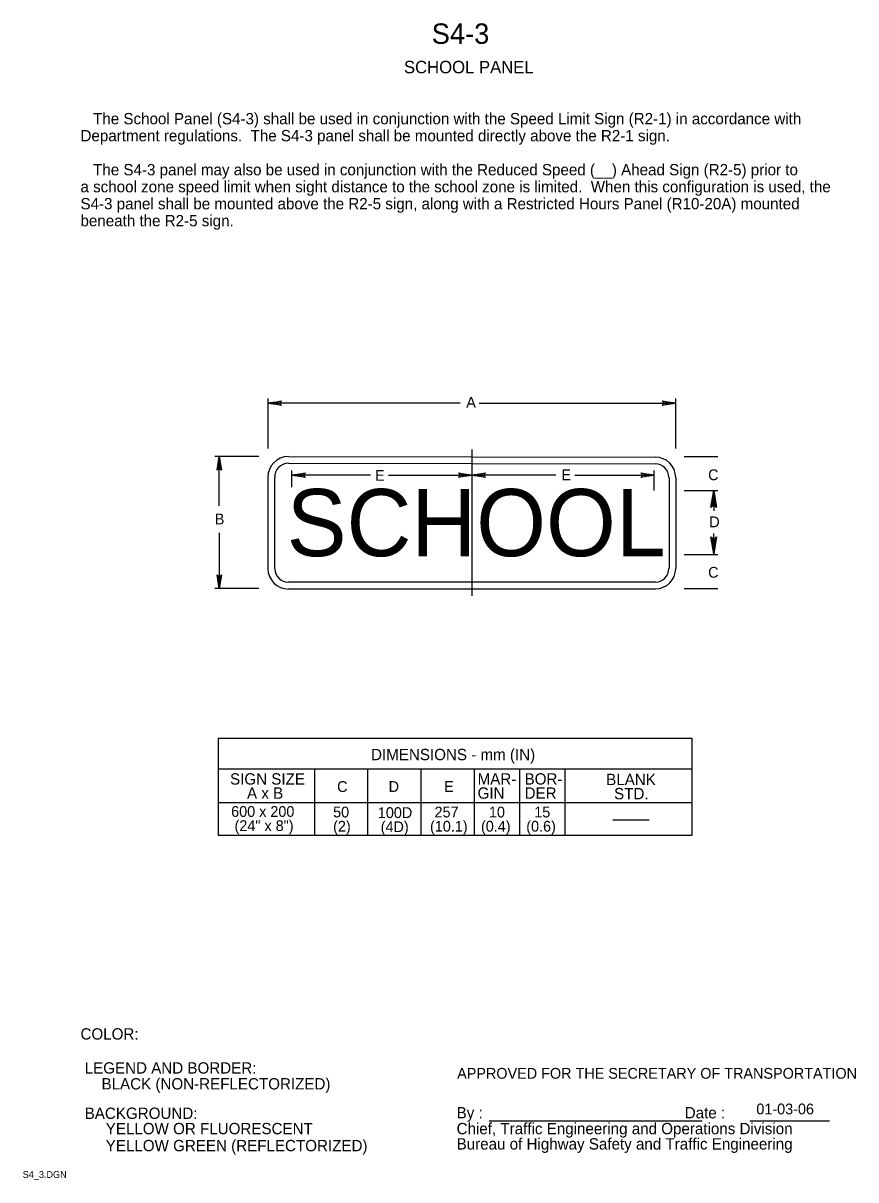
# Model space of a CAD drawing. Extents: x 0.013 to 0.196, y 0.004 to 0.259.
import ezdxf

# ---------------------------------------------------------------- set-up
doc = ezdxf.new("R2010")
doc.units = 0
for name, color, linetype in [('1', 7, 'Continuous'), ('2', 7, 'Continuous'), ('3', 7, 'Continuous'), ('4', 7, 'Continuous')]:
    doc.layers.add(name, color=color, linetype=linetype)

# ---------------------------------------------------------------- blocks, each defined once
blk = doc.blocks.new('RARROW')
at = {"layer": '3'}
for p, q in [((-2.156, 0.285), (-2.2665, 0.384625)), ((-2.2665, 0.384625), (0, 0)), ((0, 0), (-2.2665, -0.379125)), ((-2.156, 0.285), (-2.075625, 0.12075)), ((0, 0), (-2.156, 0.285)), ((-2.14975, -0.2705), (0, 0)), ((-2.075625, 0.12075), (0, 0)), ((0, 0), (-2.074, -0.108)), ((-2.2665, -0.379125), (-2.14975, -0.2705)), ((-2.074, -0.108), (-2.14975, -0.2705))]:
    blk.add_line(p, q, dxfattribs=at)

msp = doc.modelspace()

# ---------------------------------------------------------------- linework, layer by layer
at = {"layer": '1'}
for p, q in [((0.11163, 0.165), (0.11163, 0.13275)), ((0.11544, 0.01695), (0.16242, 0.01695)), ((0.17295, 0.01695), (0.19056, 0.01695))]:
    msp.add_line(p, q, dxfattribs=at)
at = {"layer": '3'}
for p, q in [((0.06663, 0.16525), (0.06663, 0.17625)), ((0.15663, 0.16525), (0.15663, 0.17625)), ((0.109, 0.17525), (0.06663, 0.17525)), ((0.11325, 0.17525), (0.15663, 0.17525)), ((0.06459, 0.1635), (0.05488, 0.1635)), ((0.05588, 0.15263), (0.05588, 0.1635)), ((0.07113, 0.1635), (0.15213, 0.16337)), ((0.1585, 0.1635), (0.16587, 0.1635)), ((0.07113, 0.162), (0.15213, 0.16187)), ((0.11163, 0.16225), (0.11163, 0.16037)), ((0.06663, 0.13875), (0.06663, 0.15888)), ((0.06813, 0.13875), (0.06813, 0.15888)), ((0.07188, 0.15675), (0.07188, 0.16037)), ((0.08925, 0.15938), (0.07188, 0.15938)), ((0.09325, 0.15938), (0.11163, 0.15938)), ((0.13012, 0.15938), (0.11163, 0.15938)), ((0.13437, 0.15938), (0.15188, 0.15938)), ((0.15188, 0.156), (0.15188, 0.16037)), ((0.15513, 0.15888), (0.15513, 0.13875)), ((0.15663, 0.15888), (0.15663, 0.13875)), ((0.1585, 0.156), (0.16587, 0.156)), ((0.165, 0.156), (0.165, 0.1515)), ((0.05588, 0.14663), (0.05588, 0.13437)), ((0.165, 0.142), (0.165, 0.1465)), ((0.1585, 0.14188), (0.16587, 0.14188)), ((0.15213, 0.13575), (0.07113, 0.13575)), ((0.06459, 0.13437), (0.05488, 0.13437)), ((0.15213, 0.13425), (0.07113, 0.13425)), ((0.1585, 0.13437), (0.16587, 0.13437)), ((0.05563, 0.10138), (0.16012, 0.10138)), ((0.05563, 0.10138), (0.05563, 0.07988)), ((0.16012, 0.10138), (0.16012, 0.07988)), ((0.16012, 0.0945), (0.05563, 0.0945)), ((0.07687, 0.0945), (0.07687, 0.07988)), ((0.07687, 0.0945), (0.07687, 0.08113)), ((0.08862, 0.0945), (0.08862, 0.07988)), ((0.10038, 0.0945), (0.10038, 0.07988)), ((0.11213, 0.0945), (0.11213, 0.07988)), ((0.12212, 0.0945), (0.12212, 0.07988)), ((0.13212, 0.0945), (0.13212, 0.07988)), ((0.16012, 0.08713), (0.05563, 0.08713)), ((0.14275, 0.08338), (0.15075, 0.08338)), ((0.16012, 0.07988), (0.05563, 0.07988))]:
    msp.add_line(p, q, dxfattribs=at)
for centre, radius, start, end in [((0.07119, 0.15891), 0.00459, 90.7913, 180.7913), ((0.1521, 0.15885), 0.0045, 0, 90), ((0.07119, 0.15891), 0.00309, 91.1755, 181.1755), ((0.1521, 0.15885), 0.003, 0, 90), ((0.07113, 0.13878), 0.00453, 179.9414, 269.9414), ((0.07109, 0.13875), 0.00297, 180.0894, 270.0894), ((0.1521, 0.13879), 0.0045, 270, 0), ((0.1521, 0.13879), 0.003, 270, 0)]:
    msp.add_arc(centre, radius, start, end, dxfattribs=at)

# ---------------------------------------------------------------- block references
for p, xscale, yscale, rotation in [((0.06663, 0.17525), 0.0013236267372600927, 0.001309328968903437, 180), ((0.05588, 0.1635), 0.0013236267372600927, 0.001309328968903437, 90), ((0.07188, 0.15938), 0.0013236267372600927, 0.001309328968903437, 180), ((0.11163, 0.15938), 0.0013236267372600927, 0.001309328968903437, 180), ((0.165, 0.156), 0.0016545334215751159, 0.0016366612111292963, 90), ((0.165, 0.142), 0.0016545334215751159, 0.0016366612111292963, -90), ((0.05588, 0.13437), 0.0013236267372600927, 0.001309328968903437, -90)]:
    msp.add_blockref('RARROW', p, dxfattribs=dict(at, xscale=xscale, yscale=yscale, rotation=rotation))
at = {"layer": '3', "xscale": 0.0013236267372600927, "yscale": 0.001309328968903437}
for p in [(0.15663, 0.17525), (0.11163, 0.15938), (0.15188, 0.15938)]:
    msp.add_blockref('RARROW', p, dxfattribs=at)

# ---------------------------------------------------------------- texts
at = {"layer": '1'}
for s, height, p in [('S4-3', 0.0045, (0.10275, 0.2545)), ('SCHOOL PANEL', 0.0027503, (0.09663, 0.248)), ('COLOR:', 0.0025, (0.02525, 0.03488)), (' LEGEND AND BORDER:', 0.0024998, (0.02525, 0.02738)), ('APPROVED FOR THE SECRETARY OF TRANSPORTATION', 0.0023752, (0.10837, 0.02625)), ('     BLACK (NON-REFLECTORIZED)', 0.0024998, (0.02525, 0.02388)), (' BACKGROUND:', 0.0024998, (0.02525, 0.01738)), ('By :                                                Date :', 0.0024998, (0.10825, 0.0175)), ('      YELLOW OR FLUORESCENT', 0.0024998, (0.02525, 0.014)), ('Chief, Traffic Engineering and Operations Division', 0.0024998, (0.10825, 0.014)), ('      YELLOW GREEN (REFLECTORIZED)', 0.0024998, (0.02525, 0.01025)), ('Bureau of Highway Safety and Traffic Engineering', 0.0024998, (0.10825, 0.01063)), ('S4_3.DGN', 0.0015, (0.0125, 0.00438))]:
    msp.add_text(s, height=height, dxfattribs=at).set_placement(p)
at = {"layer": '2'}
for s, height, p in [('   The School Panel (S4-3) shall be used in conjunction with the Speed Limit Sign (R2-1) in accordance with', 0.00249975, (0.02525, 0.23675)), ('Department regulations.  The S4-3 panel shall be mounted directly above the R2-1 sign.', 0.0024998, (0.02525, 0.233)), ('   The S4-3 panel may also be used in conjunction with the Reduced Speed (__) Ahead Sign (R2-5) prior to', 0.00249975, (0.02525, 0.2255)), ('a school zone speed limit when sight distance to the school zone is limited.  When this configuration is used, the', 0.00249975, (0.02525, 0.22175)), ('S4-3 panel shall be mounted above the R2-5 sign, along with a Restricted Hours Panel (R10-20A) mounted', 0.00249975, (0.02525, 0.218)), ('beneath the R2-5 sign.', 0.0024998, (0.02525, 0.21425))]:
    msp.add_text(s, height=height, dxfattribs=at).set_placement(p)
at = {"layer": '3'}
for s, height, p in [('A', 0.00238, (0.11038, 0.17425)), ('E', 0.00238, (0.09025, 0.15813)), ('E', 0.00238, (0.13137, 0.15825)), ('C', 0.00238, (0.16375, 0.15825)), ('SCHOOL', 0.014813, (0.07075, 0.1415)), ('B', 0.00238, (0.05488, 0.1485)), ('D', 0.00238, (0.164, 0.14788)), ('C', 0.00238, (0.16375, 0.13675)), ('DIMENSIONS - mm (IN) ', 0.0024998, (0.08937, 0.0965)), ('SIGN SIZE', 0.0025, (0.05825, 0.09112)), ('C', 0.00238, (0.08188, 0.0895)), ('D', 0.00238, (0.09325, 0.0895)), ('E', 0.00238, (0.1055, 0.0895)), ('MAR-', 0.0025, (0.11288, 0.09112)), ('BOR-', 0.0025, (0.12325, 0.09112)), ('BLANK', 0.0025, (0.14125, 0.091)), ('A x B', 0.0025, (0.062, 0.088)), ('GIN', 0.0025, (0.11288, 0.088)), ('DER', 0.0025, (0.12325, 0.088)), ('STD.', 0.0025, (0.143, 0.08788)), ('600 x 200', 0.002375, (0.0585, 0.084)), ('50', 0.002375, (0.081, 0.08388)), ('100D', 0.002375, (0.09087, 0.08375)), ('257', 0.002375, (0.10338, 0.08388)), ('10', 0.002375, (0.11538, 0.08388)), ('15', 0.002375, (0.12538, 0.08388)), ('(24" x 8")', 0.002375, (0.05925, 0.08088)), ('(2)', 0.002375, (0.081, 0.08075)), ('(4D)', 0.002375, (0.0915, 0.08063)), ('(10.1)', 0.002375, (0.10238, 0.08075)), ('(0.4)', 0.002375, (0.11363, 0.08075)), ('(0.6)', 0.002375, (0.12362, 0.08075))]:
    msp.add_text(s, height=height, dxfattribs=at).set_placement(p)
at = {"layer": '4'}
msp.add_text('01-03-06', height=0.002375, dxfattribs=at).set_placement((0.17439, 0.01839))

doc.saveas('drawing.dxf')
